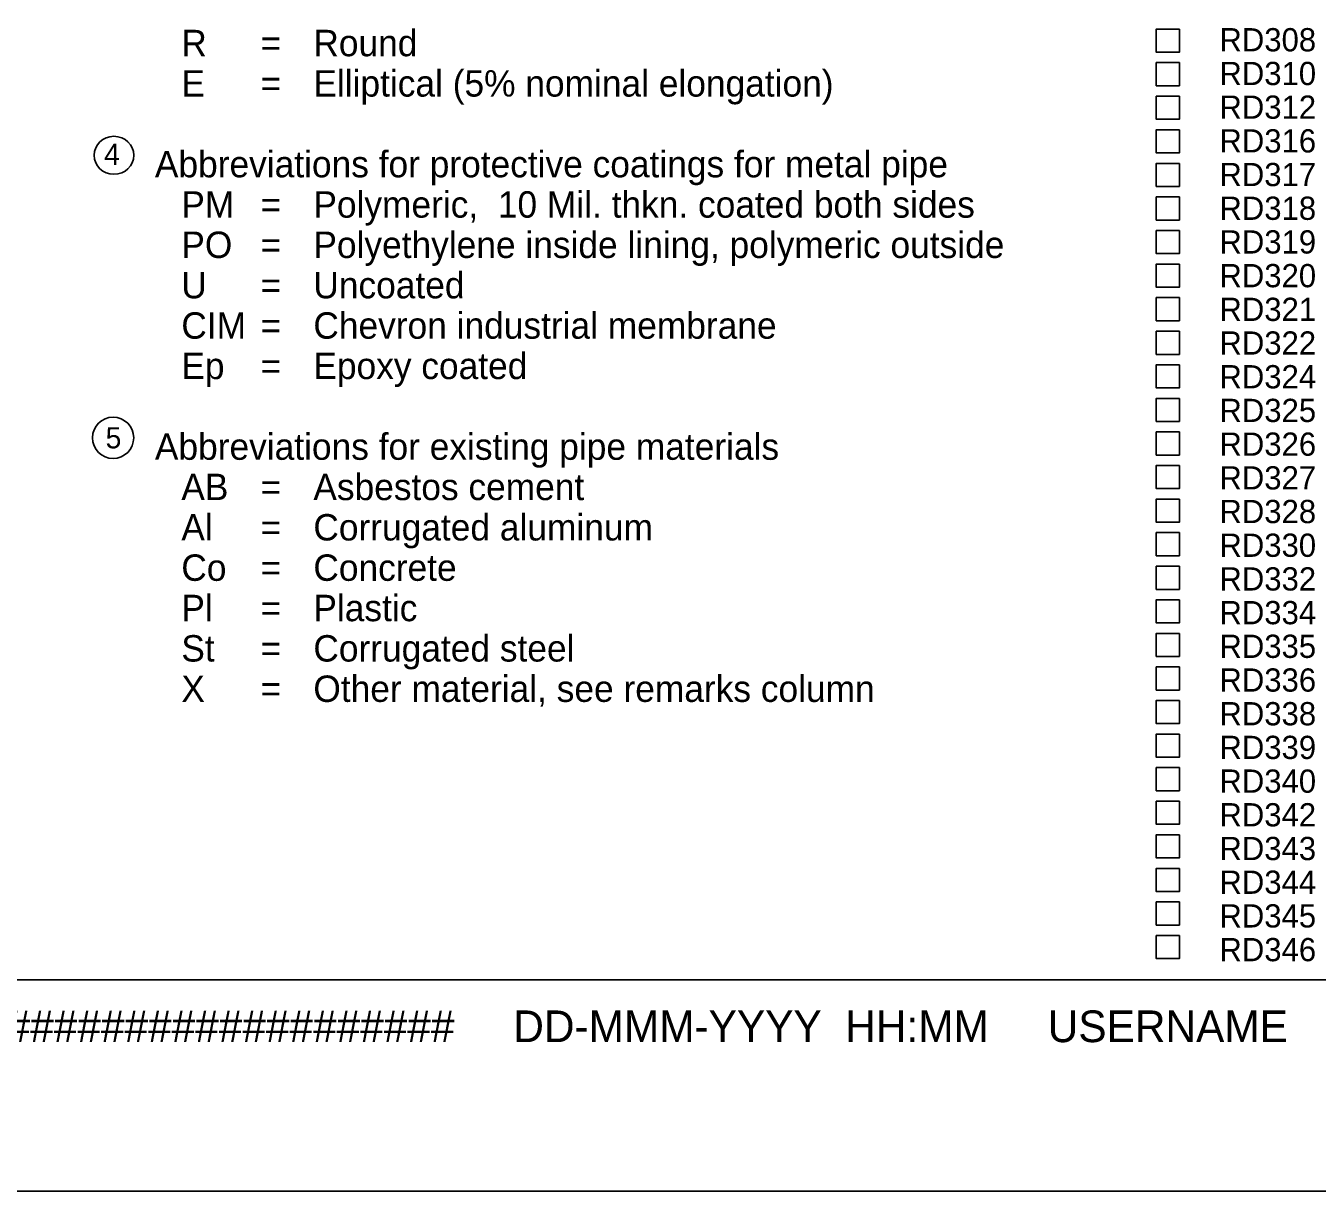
# Model space of a CAD drawing. Extents: x 0 to 1.42, y 0 to 0.92.
# Drawn here: x 0.2562 to 0.5109, y 0 to 0.2298 of the extents above; entities that cross this region are included whole.
import ezdxf

# ---------------------------------------------------------------- set-up
doc = ezdxf.new("R2010")
doc.units = 0
for name, color, linetype in [('#plot_border', 7, 'Continuous'), ('#plot_shape', 7, 'Continuous'), ('P_ODOT_PLAN_Border', 7, 'Continuous'), ('P_RDWY_PLAN_NotesTx', 7, 'Continuous')]:
    doc.layers.add(name, color=color, linetype=linetype)

msp = doc.modelspace()

# ---------------------------------------------------------------- linework, layer by layer
at = {"layer": '#plot_shape'}
msp.add_lwpolyline([(0, 0), (1.41667, 0), (1.41667, 0.91667), (0, 0.91667)], close=True, dxfattribs=at)
at = {"layer": 'P_ODOT_PLAN_Border'}
msp.add_lwpolyline([(0.0625, 0.04167), (1.39583, 0.04167), (1.39583, 0.875), (0.0625, 0.875)], close=True, dxfattribs=at)
at = {"layer": 'P_RDWY_PLAN_NotesTx'}
for points in [[(0.48373, 0.22919), (0.47917, 0.22919), (0.47917, 0.22463), (0.48373, 0.22463)], [(0.48373, 0.22257), (0.47917, 0.22257), (0.47917, 0.21801), (0.48373, 0.21801)], [(0.48373, 0.21595), (0.47917, 0.21595), (0.47917, 0.21139), (0.48373, 0.21139)], [(0.48373, 0.20933), (0.47917, 0.20933), (0.47917, 0.20477), (0.48373, 0.20477)], [(0.48373, 0.2027), (0.47917, 0.2027), (0.47917, 0.19815), (0.48373, 0.19815)], [(0.48373, 0.19608), (0.47917, 0.19608), (0.47917, 0.19153), (0.48373, 0.19153)], [(0.48373, 0.18946), (0.47917, 0.18946), (0.47917, 0.1849), (0.48373, 0.1849)], [(0.48373, 0.18284), (0.47917, 0.18284), (0.47917, 0.17828), (0.48373, 0.17828)], [(0.48373, 0.17622), (0.47917, 0.17622), (0.47917, 0.17166), (0.48373, 0.17166)], [(0.48373, 0.1696), (0.47917, 0.1696), (0.47917, 0.16504), (0.48373, 0.16504)], [(0.48373, 0.16298), (0.47917, 0.16298), (0.47917, 0.15842), (0.48373, 0.15842)], [(0.48373, 0.15636), (0.47917, 0.15636), (0.47917, 0.1518), (0.48373, 0.1518)], [(0.48373, 0.14974), (0.47917, 0.14974), (0.47917, 0.14518), (0.48373, 0.14518)], [(0.48373, 0.14312), (0.47917, 0.14312), (0.47917, 0.13856), (0.48373, 0.13856)], [(0.48373, 0.13649), (0.47917, 0.13649), (0.47917, 0.13194), (0.48373, 0.13194)], [(0.48373, 0.12987), (0.47917, 0.12987), (0.47917, 0.12531), (0.48373, 0.12531)], [(0.48373, 0.12325), (0.47917, 0.12325), (0.47917, 0.11869), (0.48373, 0.11869)], [(0.48373, 0.11663), (0.47917, 0.11663), (0.47917, 0.11207), (0.48373, 0.11207)], [(0.48373, 0.11001), (0.47917, 0.11001), (0.47917, 0.10545), (0.48373, 0.10545)], [(0.48373, 0.10339), (0.47917, 0.10339), (0.47917, 0.09883), (0.48373, 0.09883)], [(0.48373, 0.09677), (0.47917, 0.09677), (0.47917, 0.09221), (0.48373, 0.09221)], [(0.48373, 0.09015), (0.47917, 0.09015), (0.47917, 0.08559), (0.48373, 0.08559)], [(0.48373, 0.08353), (0.47917, 0.08353), (0.47917, 0.07897), (0.48373, 0.07897)], [(0.48373, 0.0769), (0.47917, 0.0769), (0.47917, 0.07235), (0.48373, 0.07235)], [(0.48373, 0.07028), (0.47917, 0.07028), (0.47917, 0.06572), (0.48373, 0.06572)], [(0.48373, 0.06366), (0.47917, 0.06366), (0.47917, 0.0591), (0.48373, 0.0591)], [(0.48373, 0.05704), (0.47917, 0.05704), (0.47917, 0.05248), (0.48373, 0.05248)], [(0.48373, 0.05042), (0.47917, 0.05042), (0.47917, 0.04586), (0.48373, 0.04586)]]:
    msp.add_lwpolyline(points, close=True, dxfattribs=at)
msp.add_circle((0.27344, 0.14858), 0.00407, dxfattribs=at)
msp.add_ellipse((0.27361, 0.20429), major_axis=(0.0039, 0), ratio=0.960077, dxfattribs=at)

# ---------------------------------------------------------------- texts
at = {"layer": '#plot_border'}
msp.add_text('THIS IS THE FILENAME LOCATION ##############################     DD-MMM-YYYY  HH:MM     USERNAME', height=0.00625, dxfattribs=at).set_placement((0.06153, 0.02939))
at = {"layer": 'P_RDWY_PLAN_NotesTx'}
for s, height, p in [('Round', 0.005208, (0.31293, 0.22383)), ('RD308', 0.004583, (0.49161, 0.22479)), ('R ', 0.005208, (0.28689, 0.22383)), ('= ', 0.005208, (0.30251, 0.22383)), ('RD310', 0.004583, (0.49161, 0.21814)), ('E ', 0.005208, (0.28689, 0.21587)), ('= ', 0.005208, (0.30251, 0.21587)), ('Elliptical (5% nominal elongation)', 0.0052083, (0.31293, 0.21587)), ('RD312', 0.004583, (0.49161, 0.2115)), ('RD316', 0.004583, (0.49161, 0.20485)), ('4', 0.00417, (0.27165, 0.2024)), ('Abbreviations for protective coatings for metal pipe', 0.0052083, (0.28168, 0.19995)), ('RD317', 0.004583, (0.49161, 0.19821)), ('PM', 0.005208, (0.28689, 0.19199)), ('Polymeric,  10 Mil. thkn. coated both sides', 0.0052083, (0.31293, 0.19199)), ('RD318', 0.004583, (0.49161, 0.19156)), ('=', 0.00521, (0.30251, 0.19199)), ('PO', 0.005208, (0.28689, 0.18404)), ('Polyethylene inside lining, polymeric outside', 0.0052083, (0.31293, 0.18404)), ('RD319', 0.004583, (0.49161, 0.18492)), ('=', 0.00521, (0.30251, 0.18404)), ('U', 0.00521, (0.28689, 0.17608)), ('Uncoated', 0.005208, (0.31293, 0.17608)), ('RD320', 0.004583, (0.49161, 0.17827)), ('=', 0.00521, (0.30251, 0.17608)), ('RD321', 0.004583, (0.49161, 0.17162)), ('CIM', 0.005208, (0.28689, 0.16812)), ('Chevron industrial membrane', 0.0052083, (0.31293, 0.16812)), ('=', 0.00521, (0.30251, 0.16812)), ('RD322', 0.004583, (0.49161, 0.16498)), ('Epoxy coated', 0.0052083, (0.31293, 0.16016)), ('Ep', 0.005208, (0.28689, 0.16016)), ('=', 0.00521, (0.30251, 0.16016)), ('RD324', 0.004583, (0.49161, 0.15833)), ('RD325', 0.004583, (0.49161, 0.15169)), ('5', 0.00417, (0.27196, 0.1465)), ('Abbreviations for existing pipe materials', 0.0052083, (0.28168, 0.14424)), ('RD326', 0.004583, (0.49161, 0.14504)), ('RD327', 0.004583, (0.49161, 0.13839)), ('AB ', 0.005208, (0.28689, 0.13629)), ('Asbestos cement', 0.0052083, (0.31293, 0.13629)), ('=', 0.00521, (0.30251, 0.13629)), ('RD328', 0.004583, (0.49161, 0.13175)), ('Al', 0.005208, (0.28689, 0.12833)), ('Corrugated aluminum', 0.0052083, (0.31293, 0.12833)), ('=', 0.00521, (0.30251, 0.12833)), ('RD330', 0.004583, (0.49161, 0.1251)), ('Co', 0.005208, (0.28689, 0.12037)), ('Concrete', 0.005208, (0.31293, 0.12037)), ('=', 0.00521, (0.30251, 0.12037)), ('RD332', 0.004583, (0.49161, 0.11846)), ('Pl', 0.005208, (0.28689, 0.11241)), ('Plastic', 0.005208, (0.31293, 0.11241)), ('=', 0.00521, (0.30251, 0.11241)), ('RD334', 0.004583, (0.49161, 0.11181)), ('St', 0.005208, (0.28689, 0.10445)), ('Corrugated steel', 0.0052083, (0.31293, 0.10445)), ('RD335', 0.004583, (0.49161, 0.10517)), ('=', 0.00521, (0.30251, 0.10445)), ('Other material, see remarks column', 0.0052083, (0.31293, 0.09649)), ('RD336', 0.004583, (0.49161, 0.09852)), ('X', 0.00521, (0.28689, 0.09649)), ('=', 0.00521, (0.30251, 0.09649)), ('RD338', 0.004583, (0.49161, 0.09187)), ('RD339', 0.004583, (0.49161, 0.08523)), ('RD340', 0.004583, (0.49161, 0.07858)), ('RD342', 0.004583, (0.49161, 0.07194)), ('RD343', 0.004583, (0.49161, 0.06529)), ('RD344', 0.004583, (0.49161, 0.05864)), ('RD345', 0.004583, (0.49161, 0.052)), ('RD346', 0.004583, (0.49161, 0.04535))]:
    msp.add_text(s, height=height, dxfattribs=at).set_placement(p)

doc.saveas('drawing.dxf')
